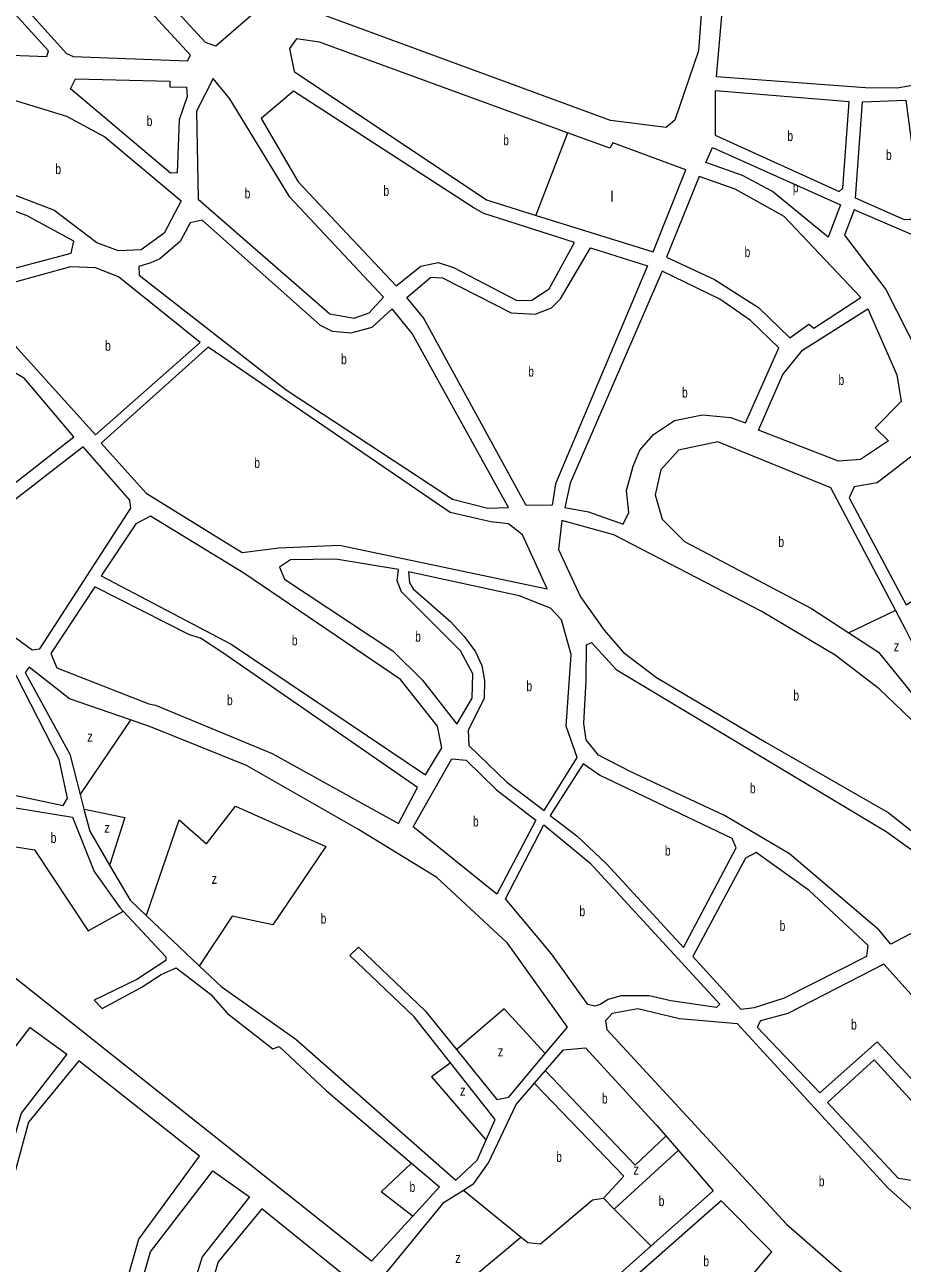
# Model space of a CAD drawing. Extents: x 639657 to 671642, y 222838 to 252123.
# Drawn here: x 646133 to 646987, y 236363 to 237569 of the extents above; entities that cross this region are included whole.
import ezdxf

# ---------------------------------------------------------------- set-up
doc = ezdxf.new("R2010")
doc.units = 0
doc.header["$LTSCALE"] = 4
doc.layers.add('1', color=7, linetype='Continuous', lineweight=13)
doc.layers.add('21', color=7, linetype='Continuous', lineweight=13)
doc.layers.add('7', color=7, linetype='Continuous')

msp = doc.modelspace()

# ---------------------------------------------------------------- linework, layer by layer
at = {"layer": '1'}
msp.add_line((646702.52, 237449.05), (646661.259, 237464.11), dxfattribs=at)
for points in [[(646101.876, 237540.425), (646154.05, 237538.42), (646155.54, 237544.01), (646038.62, 237672.86), (646019.69, 237684.42), (645857.17, 237738.84), (645853.33, 237730.45), (645854.86, 237715.64), (645880.767, 237690.235)], [(646801.37, 237717.41), (646788.84, 237543.82), (646765.79, 237476.33), (646757.42, 237469.44), (646703.07, 237476.2), (646374.39, 237597.09), (646318.64, 237548.43), (646308.54, 237552.06), (646259.24, 237606.09)], [(646661.259, 237464.11), (646419.5, 237552.35), (646397.36, 237555.74), (646390.3, 237546.27), (646395.08, 237523.72), (646582.33, 237398.71), (646630.632, 237383.676)], [(646630.632, 237383.676), (646744.68, 237348.18), (646776.49, 237427.96), (646705.3, 237454.21), (646702.52, 237449.05)], [(647067.386, 237178.906), (647099.7, 237320.67), (646940.31, 237389.04), (646931.14, 237364.31), (646971.24, 237311.56), (647002.77, 237249.33), (647015.21, 237197.889)], [(647010.665, 237178.323), (647002.58, 237153.73), (646962.91, 237123.13), (646940.57, 237119.21), (646935.44, 237108.67)], [(646980.834, 236999.127), (646917.8, 237118.29), (646807.67, 237163.14), (646769.23, 237155.1), (646752.09, 237135.94), (646746.57, 237111.44), (646753.5, 237087.82), (646775.04, 237065.96), (646898.97, 237000.73), (646935.174, 236977.201), (646964.18, 236958.35)], [(646935.44, 237108.67), (646990.92, 237004.39), (647006.8, 237014.1), (647037.23, 237046.61), (647063.255, 237160.785)], [(645947.774, 236879.854), (646007.69, 236843.28), (646170, 236808.87), (646174.06, 236816.18), (646166.01, 236853.76), (646118.08, 236947.52), (646051.55, 236999.35), (646039.899, 237019.884), (646024.458, 237047.097)], [(646964.18, 236958.35), (647061.954, 236837.78), (646990.55, 236980.76), (646980.834, 236999.127)], [(646235.544, 236892.317), (646176.18, 236912.86), (646136.99, 236943.7), (646132.93, 236938.32)], [(646132.93, 236938.32), (646176.31, 236858.94), (646186.513, 236819.679), (646190.202, 236805.484)], [(646639.601, 236567.199), (646661.08, 236592.84), (646602.86, 236674.77), (646533.94, 236738.62), (646457.76, 236785.49), (646348.45, 236847.75), (646255.1, 236885.55), (646235.544, 236892.317)], [(646087.563, 236812.381), (646179.05, 236797.42), (646200.24, 236744.62), (646225.25, 236709.45), (646228.505, 236705.977)], [(646190.202, 236805.484), (646195.84, 236783.79), (646215.137, 236750.802)], [(646215.137, 236750.802), (646235.12, 236716.64), (646250.861, 236701.697), (646302.49, 236652.682)], [(646510.342, 236408.728), (646470.33, 236364.99), (646033.85, 236711.4), (645977.63, 236727.75), (645918.26, 236705.34), (645861.38, 236660.97), (645798.76, 236661.11)], [(646228.505, 236705.977), (646270.06, 236661.64), (646270.07, 236657.99), (646241.75, 236639.45), (646200.12, 236619.37), (646207.87, 236611.02), (646245.85, 236631.51), (646265.37, 236644.45), (646280.18, 236650.93), (646313.33, 236625.01), (646330.14, 236606.15), (646374.27, 236571.88), (646380.28, 236574.25), (646426.31, 236530.85), (646509.312, 236460.53)], [(646547.339, 236558.174), (646511.94, 236603.01), (646449.26, 236662.8), (646457.62, 236670.77), (646522.66, 236609.05), (646553.166, 236571.305)], [(646302.49, 236652.682), (646323.77, 236632.48), (646396.61, 236581.47), (646552.3, 236443.92), (646573.1, 236463.52), (646581.883, 236483.124)], [(646553.166, 236571.305), (646592.5, 236522.64), (646604.1, 236524.82), (646639.601, 236567.199)], [(646639.729, 236550.736), (646657.24, 236571.03), (646678.72, 236573.02), (646747.66, 236497.99), (646757.091, 236487.036), (646769.217, 236472.953)], [(646581.883, 236483.124), (646590.83, 236503.09), (646547.339, 236558.174)], [(646559.809, 236434.283), (646569.9, 236440.65), (646584.25, 236460.87), (646611.18, 236517.65), (646629.031, 236538.338), (646639.729, 236550.736)], [(646769.217, 236472.953), (646803.04, 236433.67), (646742.709, 236379.948)], [(646509.312, 236460.53), (646536.59, 236437.42), (646510.342, 236408.728)], [(646522.53, 236310.238), (646485.34, 236354.38), (646540.96, 236422.39), (646559.809, 236434.283)], [(646742.709, 236379.948), (646712.57, 236353.11), (646584.94, 236267.15)]]:
    msp.add_lwpolyline(points, dxfattribs=at)
for points in [[(646065.26, 237670.98), (646061.41, 237664.96), (646173.16, 237541.26), (646179.61, 237538.48), (646291.11, 237534.21), (646293.89, 237539.59), (646231.88, 237607.33), (646210.15, 237620.6)], [(647020.15, 237594.39), (647027.47, 237590.54), (647021.49, 237575.7), (647023.45, 237566.04), (647032.29, 237551.67), (647034.26, 237537.71), (647022.72, 237514.91), (646982.34, 237507.51), (646951.62, 237507.87), (646806.34, 237518.69), (646817.2, 237641.6), (646933.26, 237630.71), (646965.29, 237623.26), (646997.77, 237610.45)], [(646273.93, 237508.82), (646290.26, 237508.43), (646290.72, 237499.63), (646282.82, 237476.84), (646281.02, 237425.06), (646274.58, 237424.83), (646177.04, 237506.87), (646181.95, 237516.55), (646273.92, 237514.41)], [(646332.41, 237497.36), (646316.24, 237516.87), (646299.99, 237485.26), (646301.5, 237399.54), (646429.63, 237287.92), (646453.27, 237283.46), (646468.08, 237288.87), (646482.01, 237303.94), (646390.66, 237401.47)], [(646009.94, 237480.05), (646112.81, 237498.77), (646173.24, 237480.44), (646210.46, 237460.12), (646284.96, 237398), (646268.28, 237366.38), (646245.97, 237350.21), (646223.85, 237349.08), (646202.77, 237356.98), (646161.01, 237388.89), (646074.12, 237421.77), (646004.39, 237467.58)], [(646569.45, 237391.37), (646394.27, 237504.6), (646362.75, 237478.1), (646399, 237416.53), (646494.45, 237314.93), (646518.46, 237334.1), (646535.21, 237337.8), (646550.05, 237332.89), (646612.01, 237300.81), (646626.41, 237301.06), (646643.35, 237312.06), (646667.95, 237357.23), (646579.78, 237385.38)], [(646935.54, 237494.29), (646805.09, 237505.15), (646804.98, 237461.97), (646925.87, 237407.05), (646929.52, 237410.28)], [(646941.79, 237400.43), (646948.43, 237494.32), (646990.75, 237495.93), (646999.74, 237427.2), (646995.99, 237379.72), (646989.54, 237379.27)], [(645924.02, 237468.67), (645917.18, 237456.63), (645936.6, 237422.73), (646059.11, 237324.63), (646077.17, 237320.16), (646177.87, 237346.83), (646180.21, 237358.43), (646135.02, 237383.25), (646066.63, 237408.65), (645976.45, 237469.66), (645964.84, 237472.85)], [(646795.81, 237435.09), (646802.43, 237449.93), (646926.98, 237393.95), (646915.24, 237362.55), (646860.99, 237406.89), (646831.51, 237422.5)], [(646847.31, 237294.07), (646877.89, 237264.5), (646896.12, 237277.86), (646901.07, 237273.79), (646946.98, 237303.55), (646872.22, 237382.64), (646824.67, 237409.17), (646789.4, 237421.54), (646757.58, 237343.05), (646804.48, 237321.25)], [(646387.06, 237213.7), (646549.33, 237107.32), (646583.73, 237098.37), (646603.71, 237099.07), (646509.82, 237268.56), (646490.42, 237292.79), (646470.48, 237274.48), (646450.09, 237269.06), (646432.25, 237270.74), (646420.63, 237276.3), (646305.42, 237379.14), (646293.82, 237376.32), (646283.98, 237358.25), (646264.26, 237341.45), (646255.46, 237337.56), (646243.65, 237333.88), (646243.89, 237325.5)], [(646649.42, 237122.38), (646646.25, 237101.32), (646620.9, 237101.26), (646520.95, 237284.06), (646504.57, 237303.78), (646527.94, 237323.39), (646539.55, 237322.98), (646606.46, 237288.77), (646629.66, 237287.54), (646645.76, 237293.59), (646654.55, 237302.42), (646683.65, 237352.12), (646739.13, 237334.63)], [(646177.26, 237333.72), (646092.02, 237310.31), (646086.47, 237296.98), (646201.53, 237169.86), (646303.36, 237259.9), (646223.91, 237323.73), (646201.54, 237332.49)], [(646658.5, 237099.2), (646681.72, 237094.96), (646715.48, 237083.01), (646721.04, 237094.19), (646718.62, 237115.88), (646725.01, 237139.32), (646731.63, 237155.01), (646744.91, 237170.3), (646765.29, 237183.88), (646792.78, 237189.53), (646820.07, 237186.81), (646834.48, 237181.68), (646866.96, 237254.59), (646839.39, 237281.38), (646809.68, 237301.93), (646753.32, 237329.51), (646663.82, 237122.84)], [(646847.18, 237174.41), (646871.11, 237228.61), (646890.17, 237252.5), (646953.67, 237292.82), (646981.98, 237228.44), (646986.34, 237202.46), (646960.84, 237176.83), (646973.97, 237163.97), (646946.52, 237145.86), (646925.25, 237144.31)], [(646207.13, 237161.71), (646250.87, 237113.05), (646344.27, 237055.27), (646379.93, 237059.86), (646439.01, 237062.37), (646641.3, 237020.1), (646617.53, 237072.68), (646603.75, 237083.17), (646586.56, 237085.06), (646547, 237094.2), (646311.32, 237255.2)], [(646139.74, 236960.47), (646147.26, 236961.56), (646235.87, 237098.62), (646234.99, 237106.35), (646189.31, 237158.23), (646074.58, 237069.44), (646067.46, 237079.74), (646180.47, 237168.09), (646132.2, 237224.69), (646116.92, 237233.89), (646105.12, 237228.71), (646016.36, 237150.94), (646005.27, 237118.91), (646027.54, 237064.18), (646086.79, 236999.01)], [(646522.94, 236838.93), (646538.77, 236864.96), (646534.64, 236886.22), (646498.64, 236931.68), (646346.04, 237035.29), (646255.01, 237090.71), (646240.63, 237083.38), (646207.03, 237032.59), (646333.75, 236966.08)], [(647053.49, 236735.78), (647091.03, 236757.57), (647078.71, 236784.61), (647010.8, 236878.55), (646964.7, 236922.48), (646921.86, 236955.46), (646849.77, 236998.04), (646706.27, 237072.67), (646655.53, 237086.51), (646652.38, 237058.36), (646673.98, 237012.01), (646696.84, 236979.84), (646715.37, 236958.19), (646747.88, 236933.56), (646854.83, 236870.22), (646973.39, 236801.98), (647044.43, 236746.5)], [(646553.54, 236888.2), (646568.3, 236913.37), (646569.1, 236937), (646557.01, 236959.53), (646499.5, 237017.18), (646495.17, 237027.7), (646496.65, 237038.87), (646435.6, 237048.82), (646391.56, 237048.29), (646380.83, 237040.96), (646385.59, 237029.37), (646491.05, 236959.59), (646519.91, 236930.87)], [(646506.32, 237036.53), (646507.21, 237025.79), (646510.88, 237020), (646547.7, 236987.86), (646560.2, 236973.93), (646571.41, 236959.13), (646577.89, 236945.4), (646580.29, 236930.58), (646579.91, 236913.18), (646564.3, 236882.21), (646565.2, 236867.39), (646602.03, 236831.6), (646638.63, 236803.97), (646670.51, 236855.61), (646659.9, 236886.09), (646664.88, 236956.13), (646655.34, 236989.62), (646644.79, 237001.2), (646614.03, 237013.16)], [(646200.83, 237021.84), (646157.8, 236956.86), (646163.85, 236942.91), (646253.54, 236907.89), (646259.78, 236906.61), (646373.56, 236859.41), (646496.63, 236791.39), (646515.24, 236826.45), (646325.39, 236957.69), (646303.66, 236972.03), (646292.91, 236975.22)], [(646679.68, 236965.41), (646684.62, 236967.78), (646708.54, 236941.41), (646971.5, 236783.71), (647005.94, 236758.87), (647035.66, 236731.44), (647048.82, 236712.14), (646976.08, 236673.73), (646964.44, 236687.66), (646877.45, 236761.79), (646814.18, 236799.23), (646722.97, 236841.77), (646691.56, 236857.8), (646679.49, 236872.81), (646677.09, 236888.92), (646679.34, 236930.6)], [(646562.44, 236852.98), (646592.16, 236824.27), (646630.27, 236794.71), (646592.42, 236722.65), (646511.04, 236788.2), (646548.47, 236854.24)], [(646644.22, 236799.26), (646670.27, 236779.34), (646699.56, 236751.7), (646774.11, 236670.67), (646825.43, 236767.68), (646821.76, 236776.91), (646692.47, 236838.47), (646676.54, 236849.39)], [(646638.23, 236790), (646683.02, 236752.95), (646809.49, 236615.54), (646806.28, 236612.09), (646761.78, 236618.65), (646740.71, 236623.54), (646713, 236623.47), (646700.97, 236619.79), (646693.03, 236615.05), (646687.88, 236613.32), (646681, 236615.23), (646645.64, 236664.34), (646600.81, 236717.95)], [(646829.92, 236610.43), (646843.45, 236612.18), (646872.64, 236621.49), (646952.9, 236662.07), (646954.16, 236672.39), (646896.44, 236726.17), (646845, 236763), (646834.7, 236757.6), (646783.37, 236661.67)], [(647010.83, 236526.86), (647051.56, 236563.05), (646969.46, 236654.38), (646875.91, 236606.25), (646849.07, 236599.31), (646845.86, 236592.85), (646906.83, 236528.98), (646962.78, 236578.74)], [(647029.91, 236265.35), (647061.83, 236303.02), (647091.85, 236330.8), (646973.2, 236436.43), (646826.7, 236596.14), (646770.18, 236601.16), (646729.76, 236610.73), (646704.63, 236606.16), (646698.21, 236599.06), (646699.52, 236590.68), (646874.45, 236400.97)], [(646071.47, 236308.82), (646029.95, 236342.08), (646082.82, 236521.51), (646137.7, 236592.66), (646173.39, 236566.64), (646129.05, 236509.21)], [(646277.25, 236023.95), (646293.93, 236025.08), (646300.19, 236034.52), (646298.19, 236048.03), (646248.99, 236134.89), (646241.49, 236156.6), (646190.4, 236200.62), (646243.76, 236386.44), (646302.71, 236467.41), (646185.31, 236560.24), (646136.24, 236500.53), (646079.41, 236292.11), (646148.74, 236186.38), (646129.61, 236160.44), (646128.44, 236147.79)], [(647139.04, 236464.44), (647098.26, 236446.73), (647062.4, 236439.55), (647033.18, 236437.76), (646983.53, 236445.59), (646914.59, 236519.55), (646960.03, 236561.12), (647007.65, 236509.03), (647060.39, 236552.98)], [(646244.58, 236171.6), (646206.29, 236205.24), (646255.04, 236374.32), (646315.88, 236453.08), (646351.63, 236427.6), (646305.24, 236369.19)], [(646811.01, 236423.81), (646728.9, 236351.44), (646765.29, 236318.44), (646794.57, 236296.38), (646860.12, 236374.3)], [(646315, 236040.81), (646297.21, 236019.01), (646296.17, 236013.54), (646301.11, 236005.58), (646432.1, 235898.86), (646445.13, 235901.44), (646452.6, 235916.38), (646396.38, 236015.81), (646392.53, 236032.92), (646340.71, 236075.56), (646394.31, 236259.51), (646455.03, 236341.92), (646363.33, 236415.92), (646320.95, 236364.51), (646257.8, 236150.83)]]:
    msp.add_lwpolyline(points, close=True, dxfattribs=at)
at = {"layer": '21'}
for points in [[(646630.632, 237383.676), (646630.822, 237384.176), (646661.069, 237463.61), (646661.259, 237464.11)], [(646935.174, 236977.201), (646935.675, 236977.441), (646980.334, 236998.887), (646980.834, 236999.127)], [(646235.544, 236892.317), (646235.206, 236891.817), (646186.851, 236820.179), (646186.513, 236819.679)], [(646087.563, 236812.381), (646087.447, 236811.881), (646079.048, 236775.75), (646142.074, 236765.794), (646194.318, 236686.976), (646228.005, 236705.699), (646228.505, 236705.977)], [(646250.861, 236701.697), (646251.034, 236702.197), (646283.051, 236794.833), (646309.588, 236771.602), (646337.784, 236808.107), (646425.687, 236769.113), (646374.272, 236692.784), (646334.467, 236701.08), (646302.82, 236653.182), (646302.49, 236652.682)], [(646190.202, 236805.484), (646190.702, 236805.381), (646229.977, 236797.322), (646215.296, 236751.301), (646215.137, 236750.802)], [(646639.601, 236567.199), (646639.141, 236567.699), (646599.507, 236610.8), (646553.667, 236571.732), (646553.166, 236571.305)], [(646547.339, 236558.174), (646546.839, 236557.81), (646528.86, 236544.729), (646581.454, 236483.623), (646581.883, 236483.124)], [(646757.091, 236487.036), (646756.931, 236486.885), (646726.98, 236458.683), (646640.203, 236550.236), (646639.729, 236550.736)], [(646629.031, 236538.338), (646629.513, 236537.838), (646716.229, 236447.927), (646696.728, 236426.916), (646696.264, 236426.416)], [(646706.809, 236415.866), (646707.309, 236416.323), (646768.717, 236472.496), (646769.217, 236472.953)], [(646510.342, 236408.728), (646509.842, 236409.117), (646479.713, 236432.562), (646508.812, 236460.058), (646509.312, 236460.53)], [(646559.809, 236434.283), (646560.309, 236433.877), (646616.154, 236388.577)], [(646616.154, 236388.577), (646622.544, 236383.393), (646634.831, 236381.856), (646685.513, 236424.879), (646696.264, 236426.416), (646706.809, 236415.866)], [(646706.809, 236415.866), (646742.209, 236380.448), (646742.709, 236379.948)], [(646616.154, 236388.577), (646615.654, 236388.159), (646523.03, 236310.656), (646522.53, 236310.238)]]:
    msp.add_lwpolyline(points, dxfattribs=at)

# ---------------------------------------------------------------- texts
at = {"layer": '7'}
for s, width, p in [('b', 0.75, (646251.331, 237470.69)), ('b', 0.75, (646598.558, 237451.96)), ('b', 0.75, (646875.352, 237456.1)), ('b', 0.75, (646971.399, 237437.6)), ('b', 0.75, (646162.354, 237423.925)), ('b', 0.75, (646346.686, 237400.165)), ('b', 0.75, (646481.951, 237402.705)), ('p', 0.75, (646880.711, 237406.24)), ('b', 0.75, (646833.658, 237343.02)), ('b', 0.75, (646210.78, 237251.79)), ('b', 0.75, (646440.653, 237238.755)), ('b', 0.75, (646622.913, 237226.69)), ('b', 0.75, (646925.156, 237218.565)), ('b', 0.75, (646772.688, 237206.26)), ('b', 0.75, (646356.076, 237137.65)), ('b', 0.75, (646866.594, 237060.745)), ('b', 0.75, (646392.728, 236964.82)), ('b', 0.75, (646512.81, 236968.51)), ('z', 0.8, (646979.02, 236959.166)), ('b', 0.75, (646621.197, 236920.25)), ('b', 0.75, (646329.515, 236906.615)), ('b', 0.75, (646881.161, 236911.145)), ('z', 0.8, (646193.489, 236871.162)), ('b', 0.75, (646838.878, 236820.755)), ('b', 0.75, (646569.079, 236788.445)), ('b', 0.75, (646157.83, 236772.432)), ('z', 0.8, (646210.075, 236782.388)), ('b', 0.75, (646756.058, 236760.03)), ('z', 0.8, (646314.564, 236732.608)), ('b', 0.75, (646672.869, 236701.045)), ('b', 0.75, (646420.738, 236693.81)), ('b', 0.75, (646867.778, 236686.715)), ('b', 0.75, (646937.383, 236590.62)), ('z', 0.8, (646593.364, 236564.704)), ('z', 0.8, (646556.504, 236526.29)), ('b', 0.75, (646694.728, 236518.608)), ('b', 0.75, (646650.189, 236461.756)), ('z', 0.8, (646725.444, 236449.464)), ('b', 0.75, (646905.996, 236438.04)), ('b', 0.75, (646507.358, 236432.562)), ('b', 0.75, (646750.017, 236418.733)), ('z', 0.8, (646551.897, 236363.418)), ('b', 0.75, (646793.445, 236360.095))]:
    msp.add_text(s, height=10, dxfattribs=dict(at, width=width)).set_placement(p)
msp.add_text('l', height=10, dxfattribs=at).set_placement((646703.047, 237397.202))

doc.saveas('drawing.dxf')
